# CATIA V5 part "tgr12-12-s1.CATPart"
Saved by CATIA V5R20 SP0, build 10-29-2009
Part number: TGR12-12-S1
Revision: 1
Definition: design
Nomenclature: TGR12-12-S1
Source: made
Description: NOT SPECIFIED
Bounding box of the stored display mesh (mm): x -22 to 0.8, y 0 to 12, z -6 to 6
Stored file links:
  C:\Users\Raffaele\Desktop\3D X SITO CF\I-MOLD\TGR-S1\tgr12-s1.step\tgr12-12-s1.CATPart
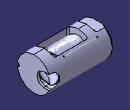
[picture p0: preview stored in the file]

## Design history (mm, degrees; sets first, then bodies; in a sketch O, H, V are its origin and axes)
Set1
  Line1 "LINE #4378": stored without definition
  DatumCurve1 "COMPOSITE_CURVE #4433"
  DatumCurve2 "COMPOSITE_CURVE #4482"
  DatumCurve3 "COMPOSITE_CURVE #4561"
  DatumCurve4 "COMPOSITE_CURVE #4604"
  DatumCurve5 "COMPOSITE_CURVE #4833"
  DatumCurve6 "COMPOSITE_CURVE #4974"
  DatumCurve7 "COMPOSITE_CURVE #5001"
  DatumCurve8 "COMPOSITE_CURVE #5059"
  DatumCurve9 "COMPOSITE_CURVE #5116"
  DatumCurve10 "COMPOSITE_CURVE #5145"
  DatumSurface1 "OPEN_SHELL #4368"
Body1 "MANIFOLD_SOLID_BREP #4369" (main body)
  Solid1: solid without history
